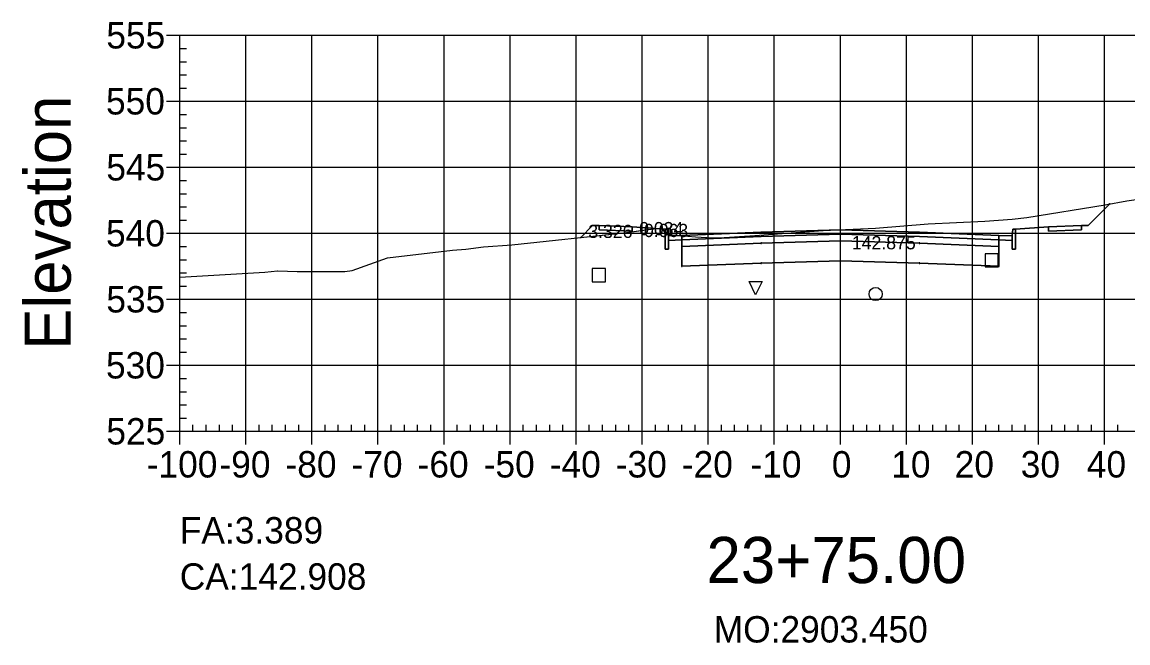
# Model space of a CAD drawing. Extents: x 704834 to 709892, y 372981 to 377533.
# Drawn here: x 705738 to 705905.4, y 373650.8 to 373744.8 of the extents above; entities that cross this region are included whole.
import ezdxf

# ---------------------------------------------------------------- set-up
doc = ezdxf.new("R2010")
doc.units = 0
for name, color, linetype in [('1', 7, 'Continuous'), ('10', 7, 'Continuous'), ('13', 7, 'Continuous'), ('14', 7, 'Continuous'), ('4', 7, 'Continuous'), ('57', 7, 'Continuous'), ('59', 7, 'Continuous'), ('60', 7, 'Continuous'), ('Default_Xsect', 7, 'Continuous'), ('Existing', 7, 'Continuous')]:
    doc.layers.add(name, color=color, linetype=linetype)

msp = doc.modelspace()

# ---------------------------------------------------------------- linework, layer by layer
for points in [[(705899.37, 373713.98), (705902.68, 373717.28)], [(705824.37, 373713.98), (705822.6, 373712.2)], [(705825.37, 373714.02), (705824.37, 373713.98)], [(705835.37, 373713.42), (705830.37, 373713.82)], [(705888.37, 373713.42), (705893.37, 373713.82)], [(705898.37, 373714.02), (705899.37, 373713.98)]]:
    msp.add_lwpolyline(points)
for points in [[(705830.37, 373713.82), (705825.37, 373714.02), (705825.37, 373713.35), (705830.37, 373713.15)], [(705893.37, 373713.15), (705898.37, 373713.35), (705898.37, 373714.02), (705893.37, 373713.82)], [(705835.87, 373712.42), (705835.79, 373713.42), (705835.37, 373713.42), (705835.37, 373710.42), (705835.87, 373710.42)], [(705837.87, 373712.5), (705835.87, 373712.42), (705835.87, 373711.75), (705837.87, 373711.83)], [(705861.87, 373712.67), (705873.87, 373712.31), (705885.87, 373711.83), (705885.87, 373712.5), (705873.87, 373712.98), (705861.87, 373713.34), (705849.87, 373712.98), (705837.87, 373712.5), (705837.87, 373711.83), (705849.87, 373712.31)], [(705861.87, 373711.67), (705873.87, 373711.31), (705885.87, 373710.83), (705885.87, 373711.83), (705873.87, 373712.31), (705861.87, 373712.67), (705849.87, 373712.31), (705837.87, 373711.83), (705837.87, 373710.83), (705849.87, 373711.31)], [(705861.82, 373712.62), (705861.92, 373712.62), (705861.92, 373712.72), (705861.82, 373712.72)], [(705885.87, 373711.83), (705887.87, 373711.75), (705887.87, 373712.42), (705885.87, 373712.5)], [(705887.87, 373710.42), (705888.37, 373710.42), (705888.37, 373713.42), (705887.96, 373713.42), (705887.87, 373712.42)], [(705837.82, 373710.78), (705837.92, 373710.78), (705837.92, 373710.88), (705837.82, 373710.88)], [(705861.87, 373708.67), (705873.87, 373708.31), (705885.87, 373707.83), (705885.87, 373710.83), (705873.87, 373711.31), (705861.87, 373711.67), (705849.87, 373711.31), (705837.87, 373710.83), (705837.87, 373707.83), (705849.87, 373708.31)], [(705849.82, 373711.26), (705849.92, 373711.26), (705849.92, 373711.36), (705849.82, 373711.36)], [(705861.82, 373711.62), (705861.92, 373711.62), (705861.92, 373711.72), (705861.82, 373711.72)], [(705873.82, 373711.26), (705873.92, 373711.26), (705873.92, 373711.36), (705873.82, 373711.36)], [(705885.82, 373710.78), (705885.92, 373710.78), (705885.92, 373710.88), (705885.82, 373710.88)], [(705861.82, 373708.62), (705861.92, 373708.62), (705861.92, 373708.72), (705861.82, 373708.72)], [(705837.82, 373707.78), (705837.92, 373707.78), (705837.92, 373707.88), (705837.82, 373707.88)], [(705849.82, 373708.26), (705849.92, 373708.26), (705849.92, 373708.36), (705849.82, 373708.36)], [(705873.82, 373708.26), (705873.92, 373708.26), (705873.92, 373708.36), (705873.82, 373708.36)], [(705885.82, 373707.78), (705885.92, 373707.78), (705885.92, 373707.88), (705885.82, 373707.88)]]:
    msp.add_lwpolyline(points, close=True)
at = {"layer": '1'}
for points in [[(705835.37, 373712.89), (705835.55, 373712.69), (705835.93, 373712.66), (705837.6, 373712.5), (705839.95, 373712.27), (705841.64, 373712.16), (705843.55, 373712.12), (705848.93, 373712.5), (705859.29, 373713.24), (705867.18, 373713.62), (705875.17, 373714.23), (705883.76, 373714.64), (705887.89, 373714.97), (705890.1, 373715.23), (705901.96, 373717.14), (705902.68, 373717.28), (705899.37, 373713.98), (705898.37, 373714.02), (705898.37, 373713.35), (705893.37, 373713.15), (705893.37, 373713.82), (705888.37, 373713.42), (705888.37, 373710.42), (705887.87, 373710.42), (705887.87, 373711.75), (705885.87, 373711.83), (705885.87, 373710.83), (705885.87, 373707.83), (705873.87, 373708.31), (705861.87, 373708.67), (705849.87, 373708.31), (705837.87, 373707.83), (705837.87, 373710.83), (705837.87, 373711.83), (705835.87, 373711.75), (705835.87, 373710.42), (705835.37, 373710.42)], [(705822.6, 373712.2), (705829.12, 373712.9), (705833.9, 373713.53), (705830.37, 373713.82), (705830.37, 373713.15), (705825.37, 373713.35), (705825.37, 373714.02), (705824.37, 373713.98)], [(705833.9, 373713.53), (705834.01, 373713.55), (705834.73, 373713.6), (705834.88, 373713.45)], [(705834.88, 373713.45), (705834.95, 373713.38), (705835.37, 373712.89), (705835.37, 373713.42)], [(705849.05, 373703.51), (705848.05, 373705.51), (705850.05, 373705.51)]]:
    msp.add_lwpolyline(points, close=True, dxfattribs=at)
at = {"layer": '10'}
msp.add_lwpolyline([(705824.3, 373705.49), (705826.3, 373705.49), (705826.3, 373707.49), (705824.3, 373707.49)], close=True, dxfattribs=at)
at = {"layer": '13'}
msp.add_circle((705867.21, 373703.62), 1, dxfattribs=at)
at = {"layer": '14'}
for points in [[(705902.68, 373717.28), (705902.68, 373717.33), (705902.68, 373717.28), (705902.63, 373717.28), (705902.68, 373717.28), (705902.68, 373717.23), (705902.68, 373717.28), (705902.73, 373717.28)], [(705822.6, 373712.2), (705822.6, 373712.25), (705822.6, 373712.2), (705822.55, 373712.2), (705822.6, 373712.2), (705822.6, 373712.15), (705822.6, 373712.2), (705822.65, 373712.2)], [(705837.87, 373712.5), (705837.87, 373712.55), (705837.87, 373712.5), (705837.82, 373712.5), (705837.87, 373712.5), (705837.87, 373712.45), (705837.87, 373712.5), (705837.92, 373712.5)], [(705849.87, 373712.98), (705849.87, 373713.03), (705849.87, 373712.98), (705849.82, 373712.98), (705849.87, 373712.98), (705849.87, 373712.93), (705849.87, 373712.98), (705849.92, 373712.98)], [(705861.87, 373713.34), (705861.87, 373713.39), (705861.87, 373713.34), (705861.82, 373713.34), (705861.87, 373713.34), (705861.87, 373713.29), (705861.87, 373713.34), (705861.92, 373713.34)], [(705873.87, 373712.98), (705873.87, 373713.03), (705873.87, 373712.98), (705873.82, 373712.98), (705873.87, 373712.98), (705873.87, 373712.93), (705873.87, 373712.98), (705873.92, 373712.98)], [(705885.87, 373712.5), (705885.87, 373712.55), (705885.87, 373712.5), (705885.82, 373712.5), (705885.87, 373712.5), (705885.87, 373712.45), (705885.87, 373712.5), (705885.92, 373712.5)]]:
    msp.add_lwpolyline(points, dxfattribs=at)
at = {"layer": '4'}
msp.add_lwpolyline([(705883.78, 373707.72), (705885.78, 373707.72), (705885.78, 373709.72), (705883.78, 373709.72)], close=True, dxfattribs=at)
at = {"layer": '57'}
for p, q in [((705759.87, 373742.82), (705761.87, 373742.82)), ((705761.87, 373742.82), (705961.87, 373742.82)), ((705761.87, 373682.82), (705761.87, 373742.82)), ((705761.87, 373682.82), (705761.87, 373742.82)), ((705771.87, 373682.82), (705771.87, 373742.82)), ((705781.87, 373682.82), (705781.87, 373742.82)), ((705791.87, 373682.82), (705791.87, 373742.82)), ((705801.87, 373682.82), (705801.87, 373742.82)), ((705811.87, 373682.82), (705811.87, 373742.82)), ((705821.87, 373682.82), (705821.87, 373742.82)), ((705831.87, 373682.82), (705831.87, 373742.82)), ((705841.87, 373682.82), (705841.87, 373742.82)), ((705851.87, 373682.82), (705851.87, 373742.82)), ((705861.87, 373682.82), (705861.87, 373742.82)), ((705871.87, 373682.82), (705871.87, 373742.82)), ((705881.87, 373682.82), (705881.87, 373742.82)), ((705891.87, 373682.82), (705891.87, 373742.82)), ((705901.87, 373682.82), (705901.87, 373742.82)), ((705761.87, 373740.82), (705762.87, 373740.82)), ((705761.87, 373738.82), (705762.87, 373738.82)), ((705761.87, 373736.82), (705762.87, 373736.82)), ((705761.87, 373734.82), (705762.87, 373734.82)), ((705759.87, 373732.82), (705761.87, 373732.82)), ((705761.87, 373732.82), (705961.87, 373732.82)), ((705761.87, 373730.82), (705762.87, 373730.82)), ((705761.87, 373728.82), (705762.87, 373728.82)), ((705761.87, 373726.82), (705762.87, 373726.82)), ((705761.87, 373724.82), (705762.87, 373724.82)), ((705759.87, 373722.82), (705761.87, 373722.82)), ((705761.87, 373722.82), (705961.87, 373722.82)), ((705761.87, 373720.82), (705762.87, 373720.82)), ((705761.87, 373718.82), (705762.87, 373718.82)), ((705761.87, 373716.82), (705762.87, 373716.82)), ((705761.87, 373714.82), (705762.87, 373714.82)), ((705759.87, 373712.82), (705761.87, 373712.82)), ((705761.87, 373712.82), (705961.87, 373712.82)), ((705761.87, 373710.82), (705762.87, 373710.82)), ((705761.87, 373708.82), (705762.87, 373708.82)), ((705761.87, 373706.82), (705762.87, 373706.82)), ((705761.87, 373704.82), (705762.87, 373704.82)), ((705759.87, 373702.82), (705761.87, 373702.82)), ((705761.87, 373702.82), (705961.87, 373702.82)), ((705761.87, 373700.82), (705762.87, 373700.82)), ((705761.87, 373698.82), (705762.87, 373698.82)), ((705761.87, 373696.82), (705762.87, 373696.82)), ((705761.87, 373694.82), (705762.87, 373694.82)), ((705759.87, 373692.82), (705761.87, 373692.82)), ((705761.87, 373692.82), (705961.87, 373692.82)), ((705761.87, 373690.82), (705762.87, 373690.82)), ((705761.87, 373688.82), (705762.87, 373688.82)), ((705761.87, 373686.82), (705762.87, 373686.82)), ((705761.87, 373684.82), (705762.87, 373684.82)), ((705763.87, 373682.82), (705763.87, 373683.82)), ((705765.87, 373682.82), (705765.87, 373683.82)), ((705767.87, 373682.82), (705767.87, 373683.82)), ((705769.87, 373682.82), (705769.87, 373683.82)), ((705773.87, 373682.82), (705773.87, 373683.82)), ((705775.87, 373682.82), (705775.87, 373683.82)), ((705777.87, 373682.82), (705777.87, 373683.82)), ((705779.87, 373682.82), (705779.87, 373683.82)), ((705783.87, 373682.82), (705783.87, 373683.82)), ((705785.87, 373682.82), (705785.87, 373683.82)), ((705787.87, 373682.82), (705787.87, 373683.82)), ((705789.87, 373682.82), (705789.87, 373683.82)), ((705793.87, 373682.82), (705793.87, 373683.82)), ((705795.87, 373682.82), (705795.87, 373683.82)), ((705797.87, 373682.82), (705797.87, 373683.82)), ((705799.87, 373682.82), (705799.87, 373683.82)), ((705803.87, 373682.82), (705803.87, 373683.82)), ((705805.87, 373682.82), (705805.87, 373683.82)), ((705807.87, 373682.82), (705807.87, 373683.82)), ((705809.87, 373682.82), (705809.87, 373683.82)), ((705813.87, 373682.82), (705813.87, 373683.82)), ((705815.87, 373682.82), (705815.87, 373683.82)), ((705817.87, 373682.82), (705817.87, 373683.82)), ((705819.87, 373682.82), (705819.87, 373683.82)), ((705823.87, 373682.82), (705823.87, 373683.82)), ((705825.87, 373682.82), (705825.87, 373683.82)), ((705827.87, 373682.82), (705827.87, 373683.82)), ((705829.87, 373682.82), (705829.87, 373683.82)), ((705833.87, 373682.82), (705833.87, 373683.82)), ((705835.87, 373682.82), (705835.87, 373683.82)), ((705837.87, 373682.82), (705837.87, 373683.82)), ((705839.87, 373682.82), (705839.87, 373683.82)), ((705843.87, 373682.82), (705843.87, 373683.82)), ((705845.87, 373682.82), (705845.87, 373683.82)), ((705847.87, 373682.82), (705847.87, 373683.82)), ((705849.87, 373682.82), (705849.87, 373683.82)), ((705853.87, 373682.82), (705853.87, 373683.82)), ((705855.87, 373682.82), (705855.87, 373683.82)), ((705857.87, 373682.82), (705857.87, 373683.82)), ((705859.87, 373682.82), (705859.87, 373683.82)), ((705863.87, 373682.82), (705863.87, 373683.82)), ((705865.87, 373682.82), (705865.87, 373683.82)), ((705867.87, 373682.82), (705867.87, 373683.82)), ((705869.87, 373682.82), (705869.87, 373683.82)), ((705873.87, 373682.82), (705873.87, 373683.82)), ((705875.87, 373682.82), (705875.87, 373683.82)), ((705877.87, 373682.82), (705877.87, 373683.82)), ((705879.87, 373682.82), (705879.87, 373683.82)), ((705883.87, 373682.82), (705883.87, 373683.82)), ((705885.87, 373682.82), (705885.87, 373683.82)), ((705887.87, 373682.82), (705887.87, 373683.82)), ((705889.87, 373682.82), (705889.87, 373683.82)), ((705893.87, 373682.82), (705893.87, 373683.82)), ((705895.87, 373682.82), (705895.87, 373683.82)), ((705897.87, 373682.82), (705897.87, 373683.82)), ((705899.87, 373682.82), (705899.87, 373683.82)), ((705903.87, 373682.82), (705903.87, 373683.82)), ((705759.87, 373682.82), (705761.87, 373682.82)), ((705761.87, 373682.82), (705961.87, 373682.82)), ((705761.87, 373682.82), (705961.87, 373682.82)), ((705761.87, 373680.82), (705761.87, 373682.82)), ((705771.87, 373680.82), (705771.87, 373682.82)), ((705781.87, 373680.82), (705781.87, 373682.82)), ((705791.87, 373680.82), (705791.87, 373682.82)), ((705801.87, 373680.82), (705801.87, 373682.82)), ((705811.87, 373680.82), (705811.87, 373682.82)), ((705821.87, 373680.82), (705821.87, 373682.82)), ((705831.87, 373680.82), (705831.87, 373682.82)), ((705841.87, 373680.82), (705841.87, 373682.82)), ((705851.87, 373680.82), (705851.87, 373682.82)), ((705861.87, 373680.82), (705861.87, 373682.82)), ((705871.87, 373680.82), (705871.87, 373682.82)), ((705881.87, 373680.82), (705881.87, 373682.82)), ((705891.87, 373680.82), (705891.87, 373682.82)), ((705901.87, 373680.82), (705901.87, 373682.82))]:
    msp.add_line(p, q, dxfattribs=at)
at = {"layer": 'Default_Xsect'}
msp.add_lwpolyline([(705822.6, 373712.2), (705824.37, 373713.98), (705825.37, 373714.02), (705830.37, 373713.82), (705835.37, 373713.42), (705835.79, 373713.42), (705835.87, 373712.42), (705837.87, 373712.5), (705849.87, 373712.98), (705861.87, 373713.34), (705873.87, 373712.98), (705885.87, 373712.5), (705887.87, 373712.42), (705887.96, 373713.42), (705888.37, 373713.42), (705893.37, 373713.82), (705898.37, 373714.02), (705899.37, 373713.98), (705902.68, 373717.28)], dxfattribs=at)
at = {"layer": 'Existing'}
msp.add_lwpolyline([(705761.87, 373706.16), (705774.75, 373706.95), (705776.66, 373707.14), (705776.73, 373707.15), (705779.66, 373707.05), (705786.85, 373707.02), (705787.99, 373707.2), (705793.34, 373709.09), (705803.18, 373710.27), (705805.18, 373710.39), (705807.86, 373710.76), (705812.13, 373711.07), (705829.12, 373712.9), (705834.01, 373713.55), (705834.73, 373713.6), (705834.95, 373713.38), (705835.55, 373712.69), (705835.93, 373712.66), (705837.6, 373712.5), (705839.95, 373712.27), (705841.64, 373712.16), (705843.55, 373712.12), (705848.93, 373712.5), (705859.29, 373713.24), (705867.18, 373713.62), (705875.17, 373714.23), (705883.76, 373714.64), (705887.89, 373714.97), (705890.1, 373715.23), (705901.96, 373717.14), (705905.22, 373717.76), (705908.11, 373718.16)], dxfattribs=at)

# ---------------------------------------------------------------- texts
msp.add_text('CA:142.908', height=4).set_placement((705761.87, 373658.82))
at = {"layer": '1'}
msp.add_text('23+75.00', height=7, dxfattribs=at).set_placement((705841.6, 373659.82))
at = {"layer": '14'}
for p in [(705825.34, 373713.97), (705898.34, 373713.97), (705825.34, 373713.3), (705830.34, 373713.1), (705893.34, 373713.1), (705898.34, 373713.3)]:
    msp.add_text('+', height=0.1, dxfattribs=at).set_placement(p)
at = {"layer": '57'}
for s, p in [('555', (705750.75, 373740.82)), ('550', (705750.7, 373730.82)), ('545', (705750.75, 373720.82)), ('540', (705750.7, 373710.82)), ('535', (705750.75, 373700.82)), ('530', (705750.7, 373690.82)), ('525', (705750.75, 373680.82)), ('-100', (705756.86, 373675.82)), ('-90', (705767.87, 373675.82)), ('-80', (705777.87, 373675.82)), ('-70', (705787.87, 373675.82)), ('-60', (705797.87, 373675.82)), ('-50', (705807.87, 373675.82)), ('-40', (705817.87, 373675.82)), ('-30', (705827.87, 373675.82)), ('-20', (705837.87, 373675.82)), ('-10', (705848.26, 373675.82)), ('0', (705860.58, 373675.82)), ('10', (705869.57, 373675.82)), ('20', (705879.18, 373675.82)), ('30', (705889.18, 373675.82)), ('40', (705899.18, 373675.82))]:
    msp.add_text(s, height=4, dxfattribs=at).set_placement(p)
at = {"layer": '59'}
for s, height, p in [('3.326', 2, (705823.71, 373712.11)), ('0.034', 2, (705831.41, 373712.53)), ('0.063', 2, (705832.14, 373712.25)), ('142.875', 2, (705863.61, 373710.39)), ('FA:3.389', 4, (705761.87, 373665.82)), ('MO:2903.450', 4, (705842.7, 373650.82))]:
    msp.add_text(s, height=height, dxfattribs=at).set_placement(p)
at = {"layer": '60'}
msp.add_text('Elevation', height=7, rotation=90, dxfattribs=at).set_placement((705745.37, 373695.18))

doc.saveas('drawing.dxf')
